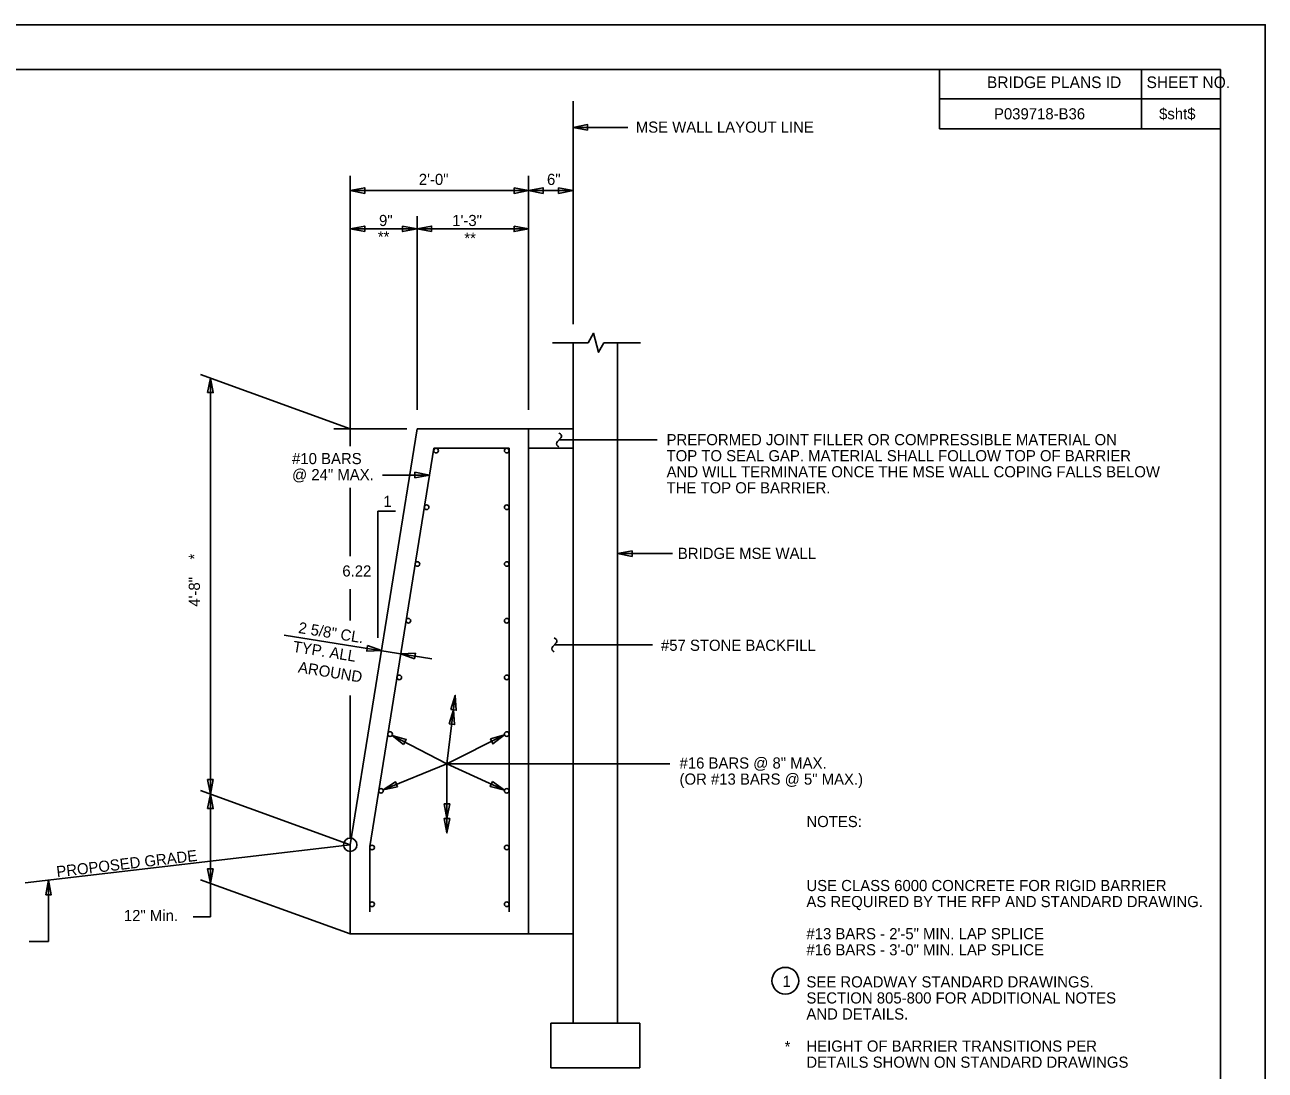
# Model space of a CAD drawing. Extents: x 96 to 240, y 601 to 689.
# Drawn here: x 184.2 to 239.8, y 642.1 to 689 of the extents above; entities that cross this region are included whole.
import ezdxf

# ---------------------------------------------------------------- set-up
doc = ezdxf.new("R2010")
doc.units = 0
for name, color, linetype in [('BR_AUTO DIMENSION', 7, 'Continuous'), ('BR_BORDER LINES', 7, 'Continuous'), ('BR_CONCRETE', 7, 'Continuous'), ('BR_REBAR', 7, 'Continuous'), ('BR_TEXT', 7, 'Continuous'), ('Level 31', 7, 'Continuous'), ('RD_XS_TieSlope', 7, 'Continuous')]:
    doc.layers.add(name, color=color, linetype=linetype)

msp = doc.modelspace()

# ---------------------------------------------------------------- linework, layer by layer
at = {"layer": 'BR_AUTO DIMENSION'}
for p, q in [((208.779, 675.573), (208.779, 685.578)), ((211.235, 684.401), (208.779, 684.401)), ((198.779, 670.105), (198.779, 682.232)), ((206.779, 671.73), (206.779, 682.232)), ((198.779, 681.566), (206.779, 681.566)), ((206.779, 681.566), (208.779, 681.566)), ((201.779, 671.73), (201.779, 680.416)), ((198.779, 679.85), (201.779, 679.85)), ((201.779, 679.85), (206.779, 679.85)), ((198.779, 670.88), (192.055, 673.316)), ((192.504, 654.486), (192.504, 673.153)), ((201.323, 670.88), (198.037, 670.88)), ((212.548, 670.386), (208.154, 670.386)), ((200.226, 668.804), (202.332, 668.804)), ((198.779, 665.164), (198.779, 668.224)), ((200.802, 667.179), (200.017, 667.179)), ((200.017, 667.179), (200.017, 661.5)), ((213.235, 665.277), (210.779, 665.277)), ((198.779, 662.281), (198.779, 663.681)), ((202.435, 660.562), (195.815, 661.626)), ((212.337, 661.192), (207.943, 661.192)), ((198.779, 652.513), (198.779, 658.909)), ((203.12, 655.842), (203.493, 658.914)), ((203.12, 655.842), (200.655, 657.123)), ((203.12, 655.842), (205.703, 657.142)), ((203.12, 655.842), (200.251, 654.684)), ((203.12, 655.842), (213.122, 655.842)), ((203.12, 655.842), (205.702, 654.67)), ((203.12, 655.842), (203.12, 652.749)), ((198.779, 652.213), (192.055, 654.649)), ((192.504, 648.989), (192.504, 654.486)), ((185.235, 647.876), (185.235, 650.623)), ((198.779, 648.213), (192.055, 650.649)), ((192.504, 648.989), (191.736, 648.989)), ((184.363, 647.876), (185.235, 647.876))]:
    msp.add_line(p, q, dxfattribs=at)
for points in [[(209.429, 684.276), (208.779, 684.401), (209.429, 684.526)], [(199.429, 681.441), (198.779, 681.566), (199.429, 681.691)], [(206.129, 681.691), (206.779, 681.566), (206.129, 681.441)], [(207.429, 681.441), (206.779, 681.566), (207.429, 681.691)], [(208.129, 681.691), (208.779, 681.566), (208.129, 681.441)], [(199.429, 679.725), (198.779, 679.85), (199.429, 679.975)], [(201.129, 679.975), (201.779, 679.85), (201.129, 679.725)], [(202.429, 679.725), (201.779, 679.85), (202.429, 679.975)], [(206.129, 679.975), (206.779, 679.85), (206.129, 679.725)], [(192.379, 672.503), (192.504, 673.153), (192.629, 672.503)], [(201.682, 668.929), (202.332, 668.804), (201.682, 668.679)], [(211.429, 665.152), (210.779, 665.277), (211.429, 665.402)], [(199.557, 661.151), (200.179, 660.925), (199.518, 660.905)], [(201.665, 660.559), (201.043, 660.786), (201.705, 660.806)], [(203.291, 658.283), (203.493, 658.914), (203.539, 658.253)], [(203.212, 657.638), (203.415, 658.268), (203.46, 657.608)], [(201.174, 656.712), (200.655, 657.123), (201.29, 656.934)], [(205.066, 656.961), (205.703, 657.142), (205.179, 656.738)], [(192.629, 655.136), (192.504, 654.486), (192.379, 655.136)], [(200.901, 654.812), (200.251, 654.684), (200.807, 655.043)], [(205.162, 655.053), (205.702, 654.67), (205.058, 654.825)], [(192.379, 653.836), (192.504, 654.486), (192.629, 653.836)], [(203.245, 654.049), (203.12, 653.399), (202.995, 654.049)], [(203.245, 653.399), (203.12, 652.749), (202.995, 653.399)], [(192.629, 651.136), (192.504, 650.486), (192.379, 651.136)], [(185.11, 649.973), (185.235, 650.623), (185.36, 649.973)]]:
    msp.add_lwpolyline(points, close=True, dxfattribs=at)
msp.add_circle((198.779, 652.213), 0.3, dxfattribs=at)
at = {"layer": 'BR_BORDER LINES'}
for p, q in [((237.837, 687.003), (103.173, 687.003)), ((225.228, 684.337), (225.228, 687.003)), ((234.293, 684.337), (234.293, 687.003)), ((237.837, 603.003), (237.837, 687.003)), ((225.228, 685.685), (237.837, 685.685)), ((234.293, 685.685), (237.837, 685.685)), ((237.837, 684.337), (225.228, 684.337))]:
    msp.add_line(p, q, dxfattribs=at)
at = {"layer": 'BR_CONCRETE'}
for p, q in [((208.779, 674.736), (208.779, 644.213)), ((210.779, 674.736), (210.779, 644.213)), ((201.779, 670.88), (198.779, 652.213)), ((206.779, 670.88), (201.779, 670.88)), ((206.779, 670.88), (208.779, 670.88)), ((206.779, 670.88), (206.779, 648.213)), ((206.779, 670.005), (208.779, 670.005)), ((198.779, 652.213), (198.779, 648.213)), ((206.779, 648.213), (198.779, 648.213)), ((206.779, 648.213), (208.779, 648.213)), ((208.779, 644.213), (207.779, 644.213)), ((207.779, 644.213), (207.779, 642.213)), ((208.779, 644.213), (210.779, 644.213)), ((210.779, 644.213), (211.779, 644.213)), ((211.779, 644.213), (211.779, 642.213)), ((211.779, 642.213), (207.779, 642.213))]:
    msp.add_line(p, q, dxfattribs=at)
at = {"layer": 'BR_REBAR'}
for p, q in [((202.525, 670.005), (199.654, 652.143)), ((205.904, 670.005), (202.525, 670.005)), ((205.904, 670.005), (205.904, 649.213)), ((199.654, 652.143), (199.654, 649.213))]:
    msp.add_line(p, q, dxfattribs=at)
for centre in [(202.629, 669.901), (205.8, 669.901), (202.203, 667.357), (205.8, 667.357), (201.795, 664.812), (205.8, 664.812), (201.386, 662.268), (205.8, 662.268), (200.977, 659.724), (205.8, 659.724), (200.568, 657.18), (205.8, 657.18), (200.159, 654.635), (205.8, 654.635), (199.758, 652.091), (205.8, 652.091), (199.758, 649.547), (205.8, 649.547)]:
    msp.add_circle(centre, 0.104, dxfattribs=at)
at = {"layer": 'BR_TEXT'}
for p, q in [((209.454, 674.736), (207.848, 674.736)), ((211.808, 674.736), (210.163, 674.736)), ((208.079, 670.304), (208.229, 670.468)), ((208.207, 670.646), (208.146, 670.688)), ((208.146, 670.071), (208.099, 670.101)), ((207.996, 661.452), (207.935, 661.495)), ((207.869, 661.111), (208.018, 661.274)), ((207.935, 660.878), (207.889, 660.907))]:
    msp.add_line(p, q, dxfattribs=at)
msp.add_lwpolyline([(209.454, 674.736), (209.701, 675.166), (209.922, 674.314), (210.163, 674.736)], dxfattribs=at)
for points in [[(206.779, 670.005), (206.779, 670.88), (208.779, 670.88), (208.779, 670.005)], [(206.779, 670.005), (208.779, 670.005), (208.779, 648.213), (206.779, 648.213)]]:
    msp.add_lwpolyline(points, close=True, dxfattribs=at)
msp.add_circle((218.305, 646.114), 0.6, dxfattribs=at)
for centre, radius, start, end in [((208.161, 670.211), 0.125, 131.007, 240.8059), ((208.154, 670.548), 0.111, 313.4519, 61.7375), ((207.943, 661.355), 0.111, 313.4519, 61.7375), ((207.95, 661.017), 0.125, 131.007, 240.8059)]:
    msp.add_arc(centre, radius, start, end, dxfattribs=at)
at = {"layer": 'Level 31'}
msp.add_lwpolyline([(95.84, 601.004), (239.84, 601.004), (239.84, 689.004), (95.84, 689.004)], close=True, dxfattribs=at)
at = {"layer": 'RD_XS_TieSlope'}
msp.add_line((198.779, 652.213), (184.192, 650.5), dxfattribs=at)

# ---------------------------------------------------------------- texts
at = {"layer": 'BR_AUTO DIMENSION'}
for s, p in [('MSE WALL LAYOUT LINE', (211.594, 684.164)), ('2\'-0"', (201.856, 681.819)), ('6"', (207.609, 681.819)), ('9"', (200.07, 679.975)), ('1\'-3"', (203.356, 679.975)), ('**', (200.016, 679.242)), ('**', (203.898, 679.179)), ('PREFORMED JOINT FILLER OR COMPRESSIBLE MATERIAL ON', (212.975, 670.141)), ('#10 BARS', (196.168, 669.292)), ('TOP TO SEAL GAP. MATERIAL SHALL FOLLOW TOP OF BARRIER', (212.975, 669.421)), ('AND WILL TERMINATE ONCE THE MSE WALL COPING FALLS BELOW ', (212.975, 668.7)), ('@ 24" MAX.', (196.168, 668.572)), ('THE TOP OF BARRIER.', (212.975, 667.98)), ('1', (200.266, 667.376)), ('BRIDGE MSE WALL', (213.481, 665.04)), ('6.22', (198.424, 664.249)), ('#57 STONE BACKFILL', (212.723, 660.916)), ('#16 BARS @ 8" MAX.', (213.556, 655.633)), ('(OR #13 BARS @ 5" MAX.)', (213.556, 654.912)), ('NOTES:', (219.251, 653.008)), ('USE CLASS 6000 CONCRETE FOR RIGID BARRIER', (219.251, 650.136)), ('AS REQUIRED BY THE RFP AND STANDARD DRAWING.', (219.251, 649.416)), ('12" Min.', (188.619, 648.789)), ('#13 BARS - 2\'-5" MIN. LAP SPLICE', (219.251, 647.975)), ('#16 BARS - 3\'-0" MIN. LAP SPLICE', (219.251, 647.254)), ('SEE ROADWAY STANDARD DRAWINGS.', (219.251, 645.814)), ('SECTION 805-800 FOR ADDITIONAL NOTES', (219.251, 645.093)), ('AND DETAILS.', (219.251, 644.373)), ('*', (218.273, 642.907)), ('HEIGHT OF BARRIER TRANSITIONS PER', (219.251, 642.932)), ('DETAILS SHOWN ON STANDARD DRAWINGS', (219.251, 642.211))]:
    msp.add_text(s, height=0.5, dxfattribs=at).set_placement(p)
for s, rotation, p in [('*', 90, (192.032, 665.012)), ('4\'-8"', 90, (192.032, 662.897)), ('2 5/8" CL.', 350.8698, (196.423, 661.721)), ('TYP. ALL', 350.8698, (196.171, 660.875)), ('AROUND', 350.8698, (196.413, 659.95)), ('PROPOSED GRADE', 6.699, (185.622, 650.753))]:
    msp.add_text(s, height=0.5, rotation=rotation, dxfattribs=at).set_placement(p)
at = {"layer": 'BR_TEXT'}
for s, height, p in [('BRIDGE PLANS ID', 0.52, (227.353, 686.166)), ('SHEET NO.', 0.52, (234.516, 686.166)), ('P039718-B36', 0.5, (227.668, 684.761)), ('$sht$', 0.5, (235.077, 684.761)), ('1', 0.5, (218.179, 645.839))]:
    msp.add_text(s, height=height, dxfattribs=at).set_placement(p)

doc.saveas('drawing.dxf')
